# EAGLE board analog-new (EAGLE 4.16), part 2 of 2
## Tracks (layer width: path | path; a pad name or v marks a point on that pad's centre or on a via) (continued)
N$472
  Top 1.016: 83.66,16.03 83.66,19.52
N$473
  Top 1.422: 79.85,12.54 79.85,16.66
N$474
  Top 1.422: 79.21,16.03 79.21,16.98
N$475
  Top 1.27: 76.35,21.42 79.21,21.42 79.85,20.79 79.85,18.25
N$476
  Top 1.27: 79.21,18.25 79.21,19.52
N$477
  Top 1.27: 76.99,16.98 76.99,18.57 77.31,18.88
N$478
  Top 1.27: 76.35,17.93 76.35,20.47 76.99,20.47 76.99,19.2
N$479
  Top 1.27: 100.8,8.09 100.8,3.01 100.17,2.38 95.09,2.38 94.45,3.01 94.45,8.09
N$480
  Top 1.27: 95.4,4.6 96.67,3.33
N$481
  Top 0.813: 95.4,8.73 95.4,11.27
N$482
  Top 0.813: 94.77,10.31 94.77,10 94.77,8.41
  Top 1.778: 94.77,6.18 94.77,10
N$483
  Top 0.813: 106.52,16.03 106.52,16.34 | 106.52,16.03 106.52,15.71 | 106.83,16.03 106.52,16.03
N$484  (via drill 0.9)
  other vias: 32.22,6.5
N$485
  Top 0.61: 102.71,14.44 102.39,14.12
N$486
  Top 0.813: 97.31,17.3 97.31,19.84
N$487
  Top 0.813: 96.67,17.61 96.67,19.2
N$488
  Top 0.813: 97.63,15.08 97.63,14.12
N$489
  Top 0.813: 97.94,14.76 97.94,14.44
N$490
  Top 0.813: 112.87,30.31 112.87,29.68 | 112.87,30.31 112.87,30.95 | 112.87,30.31 113.18,30.31 114.14,31.27
N$491
  Top 0.813: 112.87,34.44 112.87,35.71
N$492
  Top 0.406: 111.6,39.52 111.6,38.57
N$493
  Top 1.016: 117.95,34.44 117.95,38.89 | 117.95,38.89 117.95,40.16 | 117.95,38.89 116.68,40.16
N$494
  Top 1.016: 118.26,35.39 117.31,34.44
N$495
  Top 1.016: 116.36,40.48 118.58,40.48
N$496
  Top 1.016: 116.04,40.79 114.14,42.7
N$497
  Top 1.27: 103.02,43.97 103.02,44.28 | 103.02,43.97 103.02,43.33 109.06,43.33 109.06,45.87 106.83,48.09 103.02,48.09 103.02,43.97
N$498  (via drill 0.9)
  other vias: 37.62,25.87
N$499
  Top 0.813: 101.44,49.37 101.44,43.33 99.53,43.33 98.58,42.38 98.58,37.62 97.63,37.62 97.63,42.38 96.99,43.02
N$500
  Top 0.813: 100.17,43.97 100.17,51.27
N$501
  Top 1.27: 116.36,50.63 118.58,50.63 | 116.36,50.63 116.04,50.63 | 116.36,50.63 116.36,49.68
N$502
  Top 1.27: 115.41,42.06 115.09,42.38
N$503
  Top 1.27: 111.28,42.06 111.91,42.7
N$504
  Top 1.27: 109.06,50.63 109.06,50.32 110.64,48.73
N$505
  Top 1.27: 89.37,40.48 89.37,49.37 88.42,50.32
N$506  (via drill 0.9)
  other vias: 37.62,18.88
N$507  (via drill 0.9)
  other vias: 36.03,46.51
N$508
  Top 0.813: 72.86,44.28 72.54,44.6
N$509  (via drill 0.9)
  Top 0.254: 20.63,35.71 20.47,35.71 20.47,35.08 | 16.82,35.39 16.98,35.39 17.3,35.08 | 20.63,35.55 20.16,35.08 | 109.37,37.3 111.91,37.3 111.91,39.52 111.6,39.84 110.96,39.84 | 100.48,44.6 100.48,46.19
  Top 0.305: 106.2,29.36 104.61,29.36 104.29,29.04 104.29,27.14 104.93,26.5 104.93,24.92 104.29,24.28 104.61,23.96 104.61,20.79 104.93,20.47 106.83,20.47 107.15,20.79 107.15,22.06 107.47,22.38 109.37,22.38 109.37,24.28 110.96,25.87 111.6,25.87 111.6,27.77 109.37,27.77 | 104.61,16.66 104.61,16.03
  Top 0.406: 25.87,44.92 26.51,44.92 27.14,45.55 | 92.23,23.33 92.55,23.01 92.86,23.01 | 96.67,23.01 97.31,23.01 D9.A | 96.67,23.01 93.82,23.01 | 93.82,23.01 92.86,23.01 | R22.1 99.53,24.28 100.8,24.28 | 105.88,24.28 104.29,24.28 100.8,24.28 | C53.2 111.05,38.16 | 113.18,35.08 113.18,36.03 | 113.18,36.03 112.55,36.03 112.55,29.36 112.87,29.36 114.45,30.95 116.99,30.95 | 113.18,36.03 114.77,34.44 116.36,34.44 117.31,35.39 117.31,38.89 113.82,42.38 112.23,42.38 111.28,41.43 | 118.9,15.08 117.95,14.12 | 92.86,23.01 92.86,23.96 | 93.18,23.33 93.18,24.92 91.28,24.92 91.28,24.6 90.64,23.96 88.1,23.96 | 93.18,23.33 93.18,23.01 92.86,22.7 89.05,22.7 88.1,21.74 | 93.82,23.01 93.5,23.01 93.18,23.33 | 100.8,24.28 100.17,24.92 | 97.31,23.65 96.67,23.01 | 97.31,22.38 96.67,23.01 | 101.44,14.44 102.71,14.76 103.02,15.08 104.61,16.66 106.83,16.66 107.15,16.34 107.15,15.71 106.83,15.39 103.66,15.39
  Top 0.61: 104.29,15.71 101.44,12.85 96.67,12.85 | 16.98,30.16 15.87,30.16 15.55,29.84 15.55,26.82 15.87,26.5 17.78,26.5 18.09,26.82 | 21.9,36.03 | 21.9,36.03 23.33,37.46 26.35,37.46 26.35,39.84 24.92,41.27 24.92,43.97 25.87,44.92 | 24.92,45.87 23.17,45.87 23.17,44.76 23.49,44.44 23.49,40.16 21.43,38.09 20.63,38.09 20.63,35.71 | 20.63,35.55 20.63,35.24 20.47,35.08 | 21.9,36.03 21.59,35.71 21.59,30.63 21.43,30.47 18.41,30.47 18.09,30.16 | IC1.4 20.78,37 20.63,37.14 IC1.5 20.63,35.71 | 16.82,30.16 IC1.13 14.12,30.16 13.17,29.2 11.74,29.2 C4.1 | 16.82,30.16 18.09,30.16 | 18.09,30.16 | 18.09,30.16 IC1.15 18.09,26.82 | 16.82,34.92 16.82,35.39 IC1.8 14.11,37 12.38,38.73 11.74,38.73 C3.2 | 16.82,30.16 16.82,34.92 | 16.82,34.92 | 20.63,35.55 20.63,34.92 16.82,34.92 | 20.63,35.55 20.63,35.71 | R7.2 | R7.2 | R7.2 17.86,23.08 C11.1 17.93,25.39 18.09,25.55 18.09,26.82 | 16.82,34.92 16.82,36.19 16.35,36.66 14.44,36.66 13.81,37.3 | 18.09,26.82 18.09,26.5 18.41,26.19 18.41,22.06 17.93,21.58 | 98.74,14.92 | BFO_IN.2 95.08,11.26 95.4,11.58 | 98.74,14.92 97.31,13.49 96.99,13.17 96.67,12.85 | 96.67,12.85 96.04,12.22 | 96.04,12.22 95.4,11.58 | 95.4,11.58 94.13,10.31 94.13,8.09 | 96.04,12.22 96.04,8.09 95.4,7.46 | 103.66,15.39 99.21,15.39 98.58,16.03 98.58,22.7 | 103.02,15.08 101.75,15.08 | C46.2 100.8,43.97 100.17,43.33 99.21,43.33 98.9,43.33
  Top 0.813: 80.16,44.92 80.16,50.63 79.53,51.27 77.31,51.27 77.31,52.22 92.55,52.22 93.18,51.59 93.18,44.28 94.13,43.33 | 77.31,41.43 75.4,41.43 75.4,42.7 | IC1.4 21.9,38.25 | 21.9,38.25 21.9,38.41 24.13,40.63 C7.- | C7.- C1.1 | 21.9,38.25 C10.2 | C7.- | R28.1 86.83,25.55 86.83,24.6 | 110.96,40.48 110.96,39.84 109.69,38.57 | 109.69,38.57 109.37,38.25 | 109.69,38.57 107.47,38.57 107.15,38.25 107.15,30.31 106.2,29.36 105.88,29.04 | 98.58,22.38 100.17,23.96 100.17,24.92 97.31,24.92 97.31,23.65 97.31,22.38 97.31,20.47 96.04,19.2 96.04,17.93 96.99,16.98 96.99,13.17 | 97.31,13.49 101.75,13.49 | 99.53,14.12 97.31,14.12 | 74.77,43.33 78.89,43.33 | 72.23,46.51 72.23,46.82 | 72.23,46.51 72.23,43.97 73.81,43.97 | 71.27,47.78 71.27,47.46 72.23,46.51 | 91.91,42.7 91.91,41.11 90.64,41.11
  Top 1.016: E_F2.1 | C31.1 28.18,50.87 E_F2.1 | C34.2 72.63,45.47 74.77,43.33 75.4,42.7 77.62,40.48 77.94,41.43 | IC5.4 88.42,23.33 86.51,25.23 R28.1 | L8.1 112.87,48.09 110.01,50.95 C44.1A | C4.1 11.74,28.89 10.24,27.39 C5.1 | 27.14,49.37 E_F2.1 | 27.14,49.37 | 27.14,45.55 27.14,49.37 | C65.- 89.37,8.09 89.46,8.18 C52.1 89.69,8.41 RF_GAIN.1 87.78,8.09 | 82.39,7.77 82.62,7.54 C51.2 87.24,7.54 87.78,8.09 | 82.39,7.77 R33.2 | 82.39,7.77 AGC_OUT.1 | TX_OUT.4 79.22,7.76 79.21,7.77 81.43,7.77 82.39,7.77 | C66.- 104.93,2.38 104.93,1.42 | 104.93,1.42 104.93,0.79 118.9,0.79 118.9,15.08 118.9,16.66 | 118.9,29.04 118.9,29.36 113.18,35.08 | 118.9,29.04 118.9,16.66 | 118.9,29.04 118.9,41.11 116.36,41.11 115.72,41.74 115.72,48.73 116.68,49.68 118.9,49.68 118.9,54.76 118.58,55.08 98.26,55.08 97.94,54.76 97.94,51.59 98.26,51.27 99.53,51.27 100.48,50.32 100.48,46.19 100.48,45.24 | 118.9,16.66 118.9,17.3 117.95,18.25 117.95,30 | 104.93,1.42 104.93,2.69 105.88,2.69 106.83,1.74 | 115.09,3.33 112.23,3.33 110.33,1.42 | 80.48,8.09 79.53,8.09 | 87.78,8.09 80.48,8.09 | 79.21,9.04 79.53,9.04 80.48,8.09 | 99.21,43.33 100.48,44.6
  Top 1.27: 110.96,39.2 110.96,39.84 110.96,47.46 108.1,50.32 102.07,50.32 101.12,49.37 | 32.86,6.98 32.54,6.66 32.54,6.98 | R15.1 58.74,44.45 58.26,43.97 C28.2 58.42,43.97 | 42.06,39.05 45.08,41.9 F1.GND 56.35,41.9 58.42,43.97 | 58.42,43.97 | C20.1 73.11,29.91 73.18,29.84 E_F1.1 73.18,24.28 76.35,21.11 77.78,21.11 | C24.2 62.79,7.84 61.75,8.88 v61.75,11.27 61.75,12.38 C16.2 | 73.25,4.67 73.34,4.76 | 73.25,4.67 C25.1 | E_TX.2 73.02,4.44 73.18,4.6 73.25,4.67 | C34.2 71.27,47.78 v67.46,47.78 67.46,50.63 67.31,50.48 C32.1 | 80.48,44.92 80.48,43.97 | 80.48,44.92 IC2.7 80.48,48.73 | 80.48,48.73 80.48,49.05 80.71,48.82 C35.2 80.48,48.73 | 80.48,48.73 80.48,50.95 | 80.48,50.95 C39.2 | 80.48,50.95 C36.1A 92.23,50.95 92.63,50.55 C42.2 92.63,45.32 91.59,44.28 | C44.1A 101.12,50.95 101.12,49.37 | 101.12,49.37 101.12,48.73 101.03,48.96 C43.2 100.8,48.73 IC3.7 100.8,43.97 | IC2.3 77.94,41.43 77.94,42.38 78.89,43.33 79.21,43.65 | 79.21,43.65 79.53,43.97 80.48,43.97 | 80.48,43.97 C38.2 | 98.26,40.79 IC3.3 | 98.26,40.79 98.26,42.38 98.9,43.33 94.13,43.33 93.5,43.33 | 98.26,40.79 C41.2 | L6.1 91.59,43.97 92.23,43.33 93.5,43.33 | C5.1 9.2,27.46 9.05,27.31 LO_IN.3 | 78.1,20.15 R30.1 | 78.1,17.61 C50.- | IC5.4 92.23,23.33 C49.2 | R22.1 99.7,24.45 99.53,24.28 | 99.53,24.28 C48.2 | 99.53,24.28 98.58,23.33 D9.A 98.03,23.24 C61.1 97.94,21.11 98.03,21.02 98.03,19.2 | C64.- 86.83,17.93 86.83,18.57 | 86.83,24.6 86.83,18.57 | IC4.14 IC4.13 | 105.88,27.46 AF_OUT.2 | 107.87,27.46 105.88,27.46 | IC4.14 105.88,24.28 105.88,27.46 | R37.1 108.1,23.65 106.83,23.65 | IC4.14 106.83,23.65 | 98.03,19.2 C60.1 97.94,17.61 97.94,15.71 98.74,14.92 99.53,14.12 R25.E 100.17,14.44 101.44,14.44 v101.75,14.44
  Top 1.27: 98.03,19.2 R25.S | 117.95,8.41 117.86,8.5 C58.2 117.86,11.18 118.26,11.58 C57.1 | 104.61,16.03 IC4.11 | C53.2 111.05,44.05 L8.1 | 109.06,26.82 107.79,28.09 | 106.83,23.65 106.83,26.82 | 86.83,18.57 86.83,17.61 88.74,17.61 88.74,17.93 87.78,18.88 87.78,23.01 | 100.17,5.23 100.17,4.92 98.26,3.01 | 93.5,43.33 92.55,43.33 91.91,42.7 89.37,40.16 89.37,37.62 | 79.21,43.65 80.48,44.92
  Top 1.422: TX_IN.2 | TX_IN.2 | TX_IN.2 27.85,7.05 | D6.A 35.89,36.37 36.03,36.51 C30.1 35.94,36.59 35.87,36.66 35.87,37.62 37.83,39.58 C27.2 40.9,40.21 41.43,39.84 | 40,14.12 C15.2 41.85,12.59 42.7,11.74 42.7,6.18 40.16,3.64 39.68,3.64 | 40,14.12 40,15.71 35.87,19.84 35.87,20.31 | 35.87,20.31 35.87,25.55 | 35.87,25.55 35.87,25.87 | 35.87,25.55 35.71,25.55 C18.1 | 41.43,39.84 | 41.43,39.84 42.06,39.05 42.06,27.77 40,25.55 35.87,25.55 | 40,14.12 40.16,14.12 F2.GND | 36.51,3.64 36.19,3.64 35.24,4.6 | 36.51,3.64 39.68,3.64 | 35.24,4.6 32.86,6.98 32.38,7.46 27.78,7.46 | 32.54,6.98 | 35.24,4.6 34.76,4.6 35.56,4.28 35.48,4.35 C22.2 | TX_IN.2 27.63,6.97 27.62,6.98 32.54,6.98 | 35.87,20.31 35.87,17.46 38.41,17.46 | 36.51,3.64 32.86,3.64 | 32.86,3.64 32.86,6.18 | 32.86,3.64 31.27,5.23 | 64.45,41.43 64.45,41.59 64.43,41.61 D8.A 64.45,41.74 64.45,41.43 | 64.45,41.43 64.45,40.79 65.72,39.52 RFC9.2 67.62,36.98 67.62,26.66 66.35,25.39 65.88,25.39 64.13,27.14 60,27.14 58.57,25.71 58.57,17.61 60.48,15.71 61.75,15.71 C16.2 | C28.2 58.42,43.97 60.64,41.43 61.75,41.43 | 61.75,41.43 64.45,41.43 | L3.2 | L4.2 78.1,17.61 L3.2 | C19.1 77.7,21.2 77.78,21.11 78.1,20.79 78.1,20.15 L3.2 | 61.75,41.43 R9.1 | 61.75,12.38 61.91,12.38 61.92,12.39 TX_OUT.2 | L4.2 | L4.2 79.21,14.92 79.21,12.54 | C25.1 73.18,4.6 74.12,5.54 TX_OUT.5 | R15.1 58.74,51.28 59.69,52.22 59.84,52.38 63.02,52.38 65.08,50.32 67.15,50.32 67.23,50.41 C32.1 | 39.68,3.64 40.95,3.64 41.91,2.69 59.84,2.69 63.18,6.03 63.18,9.52 64.45,10.79 71.43,10.79 73.02,9.2 | 11.58,39.05 11.74,38.89 C3.2 | 11.58,39.05 C6.- | 11.58,39.05 | LO_IN.4 3.96,22.38 | LO_IN.4 | LO_IN.4 3.49,22.85 R3.1 R5.1
  Top 1.422: C12.- 18.89,3.49 19.84,4.44 19.84,7.3 20.16,6.98 | 20.16,6.98 15.55,11.58 | 15.55,11.58 14.12,13.01 7.3,13.01 8.73,15.08 9.04,17.14 | 15.55,11.58 15.55,10.15 16.66,10.15 | 20.16,6.98 21.11,5.71 | C53.2 109.37,38.25 107.79,38.25 v107.79,32.85 C54.2 107.87,27.46 107.87,26.82 | 107.87,26.82 107.87,26.59 | 107.87,26.82 109.06,26.82 C55.2 | +-5V1.P$1 81.59,7.62 81.43,7.77 | C66.- 105.56,1.42 110.33,1.42 113.5,1.42 117.95,5.87 117.95,8.41 C59.2 | BFO_IN.4 99.86,3 99.85,3.01 99.84,3 | 105.88,24.28 IC4.13 | 91.28,42.7 L6.1 91.59,44.28
  Top 1.676: +-5V.P$1 12.06,3.17 C12.- | 20.46,6.57 20.54,6.57 20.8,6.83 22.37,6.83 | 20.16,6.98 20.63,6.98 21.43,6.18 21.43,2.69 22.39,1.73 TX_IN.4 | BFO_IN.5 98.26,3.01 BFO_IN.4 | BFO_IN.4 | BFO_IN.3 100.18,3.02 BFO_IN.4
  Top 1.778: BFO_IN.5 95.08,3.02 BFO_IN.2
  Top 1.93: TX_OUT.5 | TX_OUT.5 | TX_OUT.2 74.12,7.31 TX_OUT.5 | TX_OUT.5 79.05,7.3 79.06,7.29 TX_OUT.4 TX_OUT.3 79.22,12.53 79.21,12.54
  Top 2.184: 22.54,1.74 22.53,1.75 TX_IN.5 22.37,6.83 L2.2 | TX_IN.4 22.54,1.74 | TX_IN.4 | TX_IN.3 22.55,1.73 22.54,1.74 | TX_IN.3 27.63,1.75 TX_IN.2 | TX_IN.3 | L2.2 | 18.57,10.79 | L2.2 18.57,10.79 | 18.57,10.79 L1.2 18.57,17.14 17.14,18.57 RFC2.2 | 3.95,17.15 LO_IN.5 | 3.95,17.15 LO_IN.4 | 3.95,17.15 3.96,17.14 9.04,17.14 9.05,17.15 LO_IN.2 | LO_IN.2 9.04,17.3 9.05,17.31 LO_IN.3 | LO_IN.2
N$510
  Top 0.813: 92.55,43.97 92.55,44.6
N$512
  Top 1.422: 90.32,41.74 90.32,43.65
N$513
  Top 1.422: 83.02,50.63 82.39,50.63 81.12,49.37
N$514
  Top 1.422: 77.62,51.59 90.01,51.59
N$515  (via drill 0.9)
  other vias: 51.91,42.06
N$516  (via drill 0.9)
  other vias: 51.91,14.12
N$517  (via drill 0.9)
  other vias: 76.99,2.06
N$518  (via drill 0.9)
  other vias: 109.06,1.1
N$519  (via drill 0.9)
  other vias: 118.26,19.52
N$520  (via drill 0.9)
  other vias: 118.58,7.14
N$521  (via drill 0.9)
  other vias: 118.26,32.85
N$522  (via drill 0.9)
  other vias: 90.64,47.14
N$523  (via drill 0.9)
  other vias: 66.83,35.08
N$524  (via drill 0.9)
  other vias: 77.31,42.38
N$525  (via drill 0.9)
  other vias: 97.94,43.02
N$526  (via drill 0.9)
  other vias: 112.87,49.05
N$527  (via drill 0.9)
  other vias: 100.17,53.49
N$528
  Top 1.422: 38.25,31.58 38.25,36.66
N$529
  Top 1.778: 35.71,25.87 41.43,25.87
N$530
  Top 1.778: 63.34,19.52 63.34,23.96
N$531
  Top 1.778: 65.88,7.46 70,7.46
N$532
  Top 1.422: 83.34,25.55 84.29,24.6 84.29,23.65
N$533
  Top 1.422: 105.56,23.01 108.42,23.01
N$534
  Top 1.422: 39.52,31.58 39.52,36.66
N$535
  Top 1.778: 22.7,20.15 27.78,20.15
N$536
  Top 0.813: 18.57,18.25 20.95,15.87
N$537
  Top 0.61: 21.11,16.03 28.09,16.03 28.09,15.39 21.43,15.39
N$538
  Top 0.61: 21.43,15.71 27.78,15.71
N$539
  Top 1.676: 3.65,14.12 3.65,19.84
N$543
  Top 1.778: 14.44,38.25 12.54,40.16
N$544
  Top 1.676: 5.87,29.68 5.87,33.81
N$545
  Top 1.676: 5.87,26.82 5.87,25.23 6.19,24.92
N$546
  Top 0.813: 95.72,8.41 95.72,11.58
N$547  (via drill 0.9)
  other vias: 87.15,21.11
N$548  (via drill 0.9)
  other vias: 107.47,26.19
N$563
  Top 0.813: 23.33,30 23.33,31.27
N$564
  Top 0.813: 23.65,29.84 23.65,31.27
N$565
  Top 0.813: 23.97,29.68 23.97,31.27
N$594
  Top 1.778: 28.41,37.62 28.41,41.43
N$615  (via drill 0.8)
  other vias: 25.55,52.06
N$616  (via drill 0.8)
  other vias: 12.54,44.28
N$617  (via drill 0.8)
  other vias: 23.81,38.41
(copper drawn outside any net)
  shapes: Top area x47

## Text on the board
Top: Slomkowski | Michal | A | 2009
